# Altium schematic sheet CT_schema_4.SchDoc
size 287 x 169 mm
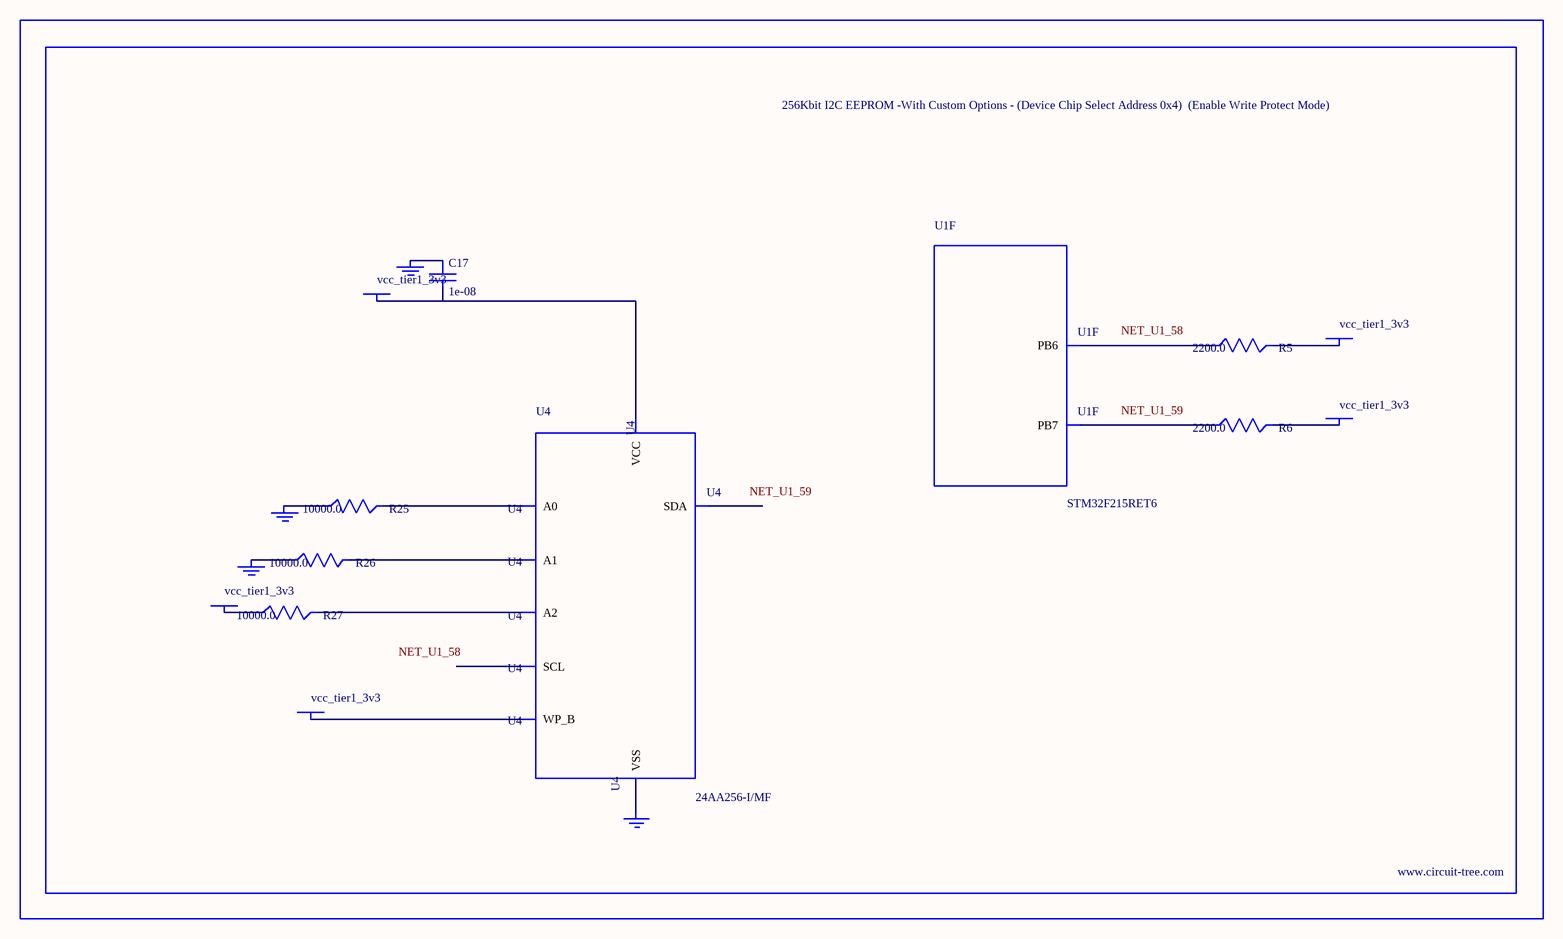
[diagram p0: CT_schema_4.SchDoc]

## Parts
BORDER3  (no value)
C17  1e-08  [C0402]
GND_INSTANCE_3_0  (no value)
GND_INSTANCE_3_1  (no value)
GND_INSTANCE_3_2  (no value)
GND_INSTANCE_3_3  (no value)
POWER_INSTANCE_3_0  vcc_tier1_3v3
POWER_INSTANCE_3_1  vcc_tier1_3v3
POWER_INSTANCE_3_2  vcc_tier1_3v3
POWER_INSTANCE_3_3  vcc_tier1_3v3
POWER_INSTANCE_3_4  vcc_tier1_3v3
R5  2200.0  [R0603]
R6  2200.0  [R0603]
R25  10000.0  [R0603]
R26  10000.0  [R0603]
R27  10000.0  [R0603]
U1  STM32F215RET6  [LQFP64]  (part F of 7)
U4  24AA256-I/MF  [DFN8-S]

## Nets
NetC17_1: C17.1 GND_INSTANCE_3_2.0(GND)
NetC17_2: C17.2 POWER_INSTANCE_3_2.0(PWR) U4.8(VCC)
NetGND_INSTANCE_3_0_0: GND_INSTANCE_3_0.0(GND) R25.1
NetGND_INSTANCE_3_1_0: GND_INSTANCE_3_1.0(GND) R26.1
NetGND_INSTANCE_3_3_0: GND_INSTANCE_3_3.0(GND) U4.4(VSS)
NetPOWER_INSTANCE_3_0_0: POWER_INSTANCE_3_0.0(PWR) R27.1
NetPOWER_INSTANCE_3_1_0: POWER_INSTANCE_3_1.0(PWR) U4.7(WP_B)
NetPOWER_INSTANCE_3_3_0: POWER_INSTANCE_3_3.0(PWR) R5.2
NetPOWER_INSTANCE_3_4_0: POWER_INSTANCE_3_4.0(PWR) R6.2
NetR5_1: R5.1 U1.58(PB6)
NetR6_1: R6.1 U1.59(PB7)
NetR25_2: R25.2 U4.1(A0)
NetR26_2: R26.2 U4.2(A1)
NetR27_2: R27.2 U4.3(A2)

Not connected (* = marked no-connect by the designer): U4 5(SDA) 6(SCL)

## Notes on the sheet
- Labels drawn without touching a wire or pin: NET_U1_58, NET_U1_59

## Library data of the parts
BORDER3 = BORDER_PAGE3
C17 = C0402C103K3RAC
GND_INSTANCE_3_0-GND_INSTANCE_3_3 = GND
POWER_INSTANCE_3_0-POWER_INSTANCE_3_4 = PWR
R5 R6 = RC0603JR-072K2L
R25-R27 = RC0603JR-0710KL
